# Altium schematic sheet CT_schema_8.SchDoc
size 252 x 159 mm
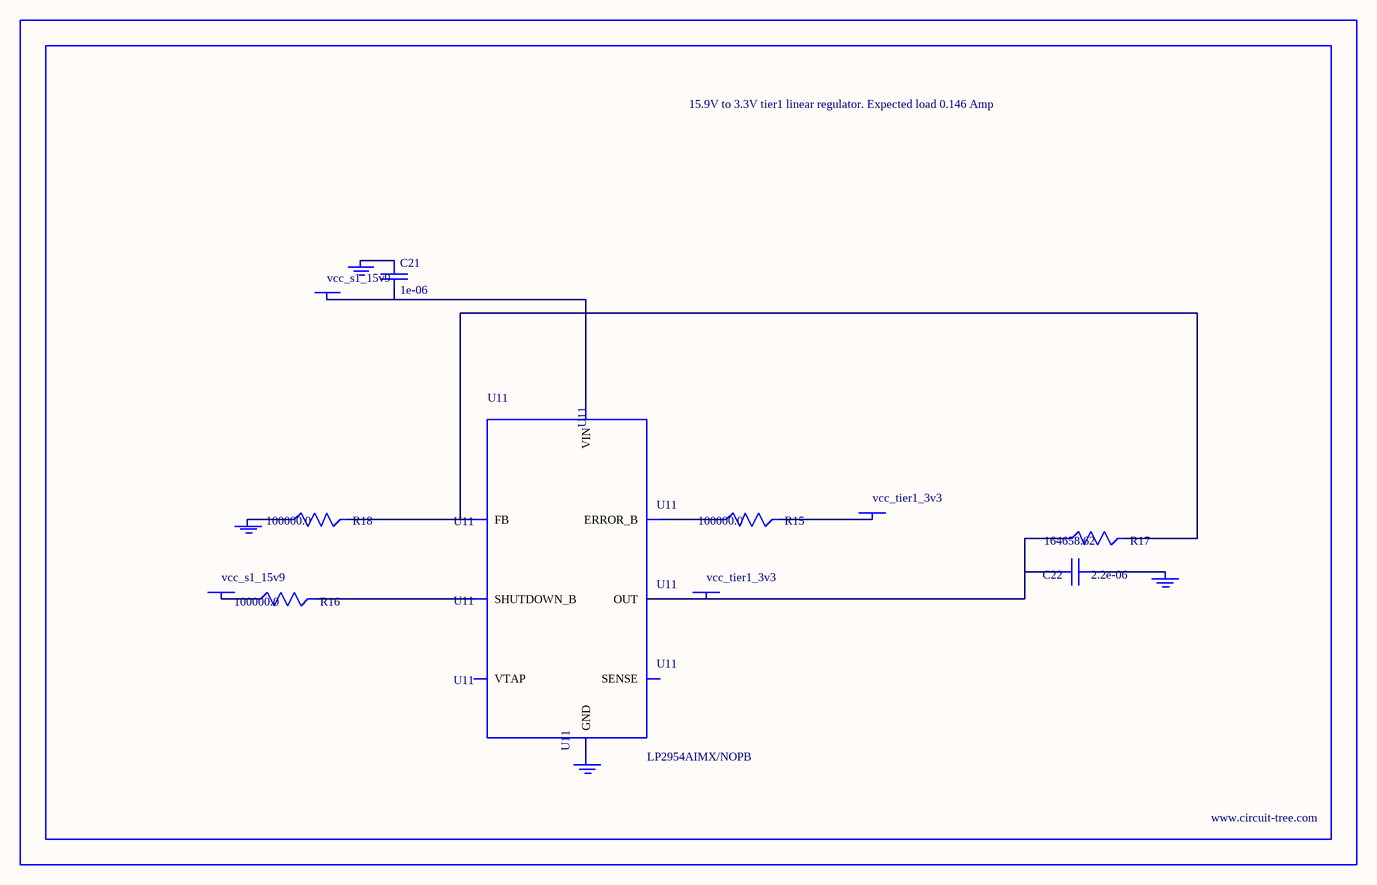
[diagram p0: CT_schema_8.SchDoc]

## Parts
BORDER7  (no value)
C21  1e-06  [EXV-9B]
C22  2.2e-06  [EXV-9B]
GND_INSTANCE_7_0  (no value)
GND_INSTANCE_7_1  (no value)
GND_INSTANCE_7_2  (no value)
GND_INSTANCE_7_3  (no value)
POWER_INSTANCE_7_0  vcc_s1_15v9
POWER_INSTANCE_7_1  vcc_tier1_3v3
POWER_INSTANCE_7_2  vcc_s1_15v9
POWER_INSTANCE_7_3  vcc_tier1_3v3
R15  100000.0  [R0603]
R16  100000.0  [R0603]
R17  164658.62  [R0603]
R18  100000.0  [R0603]
U11  LP2954AIMX/NOPB  [LP2954]

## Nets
NetC21_1: C21.1 GND_INSTANCE_7_2.0(GND)
NetC21_2: C21.2 POWER_INSTANCE_7_2.0(PWR) U11.8(VIN)
NetC22_1: C22.1 GND_INSTANCE_7_0.0(GND)
NetC22_2: C22.2 POWER_INSTANCE_7_3.0(PWR) R17.1 U11.1(OUT)
NetGND_INSTANCE_7_1_0: GND_INSTANCE_7_1.0(GND) R18.1
NetGND_INSTANCE_7_3_0: GND_INSTANCE_7_3.0(GND) U11.4(GND)
NetPOWER_INSTANCE_7_0_0: POWER_INSTANCE_7_0.0(PWR) R16.1
NetPOWER_INSTANCE_7_1_0: POWER_INSTANCE_7_1.0(PWR) R15.2
NetR15_1: R15.1 U11.5(ERROR_B)
NetR16_2: R16.2 U11.3(SHUTDOWN_B)
NetR17_2: R17.2 R18.2 U11.7(FB)

Not connected (* = marked no-connect by the designer): U11 2(SENSE) 6(VTAP)

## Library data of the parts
BORDER7 = BORDER_PAGE7
C21 = EDK105M050A9BAA
C22 = EDK225M050A9BAA
GND_INSTANCE_7_0-GND_INSTANCE_7_3 = GND
POWER_INSTANCE_7_0-POWER_INSTANCE_7_3 = PWR
R15 R16 R18 = RC0603JR-07100KL
R17 = R17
